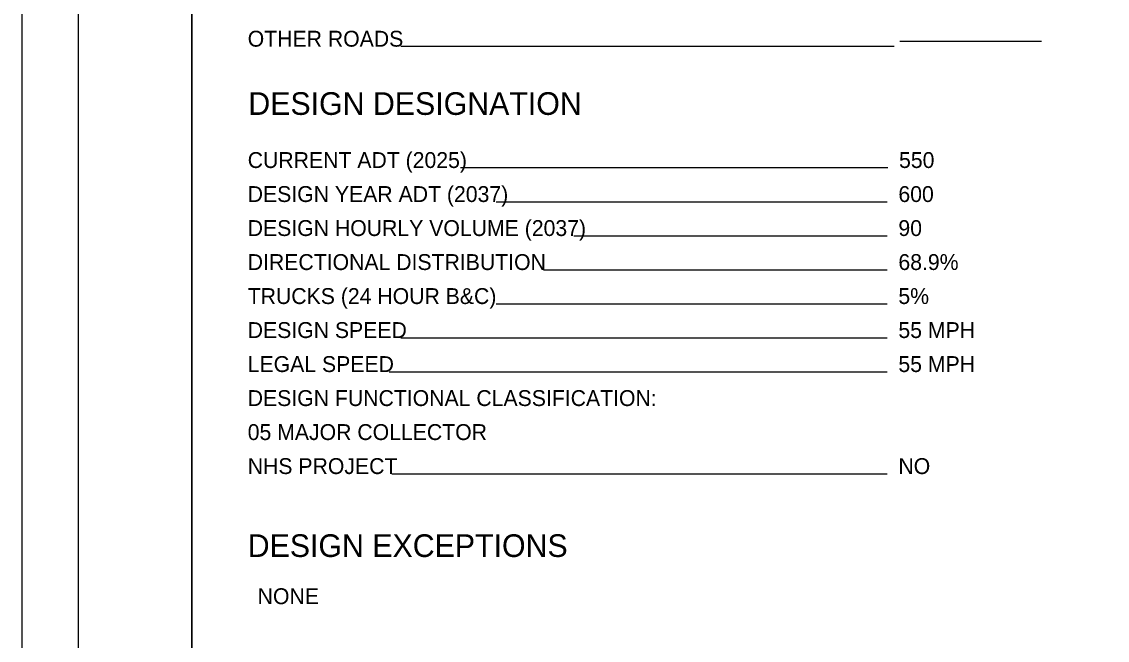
# Model space of a CAD drawing. Extents: x 0 to 82.7, y -0.2 to 22.
# Drawn here: x 0 to 9.58, y 5.64 to 11.1 of the extents above; entities that cross this region are included whole.
import ezdxf

# ---------------------------------------------------------------- set-up
doc = ezdxf.new("R2010")
doc.units = 0
for name, color, linetype in [('Default', 7, 'Continuous'), ('SH_Border', 7, 'Continuous'), ('SH_Cut_Line', 7, 'Continuous'), ('SH_Data', 7, 'Continuous'), ('SH_Text', 7, 'Continuous')]:
    doc.layers.add(name, color=color, linetype=linetype)

msp = doc.modelspace()

# ---------------------------------------------------------------- linework, layer by layer
at = {"layer": 'SH_Border'}
for points in [[(0.5, 21.5), (1.5, 21.5), (1.5, 0.5), (0.5, 0.5)], [(1.5, 21.5), (33.5, 21.5), (33.5, 0.5), (1.5, 0.5)]]:
    msp.add_lwpolyline(points, close=True, dxfattribs=at)
at = {"layer": 'SH_Cut_Line'}
msp.add_lwpolyline([(0, 0), (34, 0), (34, 22), (0, 22)], close=True, dxfattribs=at)
at = {"layer": 'SH_Data'}
for p, q in [((9, 10.9223), (7.75, 10.9223)), ((7.7, 10.8767), (3.3471, 10.8767)), ((7.6424, 9.8062), (3.871, 9.8062)), ((7.6368, 9.5062), (4.1885, 9.5062)), ((7.6368, 9.2062), (4.8723, 9.2062)), ((7.6368, 8.9062), (4.6037, 8.9062)), ((7.6368, 8.6062), (4.1885, 8.6062)), ((7.6368, 8.3062), (3.346, 8.3062)), ((7.6368, 8.0062), (3.2422, 8.0062)), ((7.6368, 7.1062), (3.2669, 7.1062))]:
    msp.add_line(p, q, dxfattribs=at)

# ---------------------------------------------------------------- texts
at = {"layer": 'Default'}
msp.add_text('NONE', height=0.14, dxfattribs=at).set_placement((2.0821, 5.9586))
at = {"layer": 'SH_Data'}
msp.add_text('DESIGN DESIGNATION', height=0.2, dxfattribs=at).set_placement((2, 10.2747))
at = {"layer": 'SH_Text'}
for s, height, p in [('OTHER ROADS', 0.14, (1.9944, 10.8767)), ('CURRENT ADT (2025)', 0.14, (1.9944, 9.8062)), ('550', 0.14, (7.7424, 9.8062)), ('DESIGN YEAR ADT (2037)', 0.14, (1.9944, 9.5062)), ('600', 0.14, (7.7368, 9.5062)), ('DESIGN HOURLY VOLUME (2037)', 0.14, (1.9944, 9.2062)), ('90', 0.14, (7.7368, 9.2062)), ('DIRECTIONAL DISTRIBUTION', 0.14, (1.9944, 8.9062)), ('68.9%', 0.14, (7.7368, 8.9062)), ('TRUCKS (24 HOUR B&C)', 0.14, (1.9944, 8.6062)), ('5%', 0.14, (7.7368, 8.6062)), ('DESIGN SPEED', 0.14, (1.9944, 8.3062)), ('55 MPH', 0.14, (7.7368, 8.3062)), ('LEGAL SPEED', 0.14, (1.9944, 8.0062)), ('55 MPH', 0.14, (7.7368, 8.0062)), ('DESIGN FUNCTIONAL CLASSIFICATION:', 0.14, (1.9944, 7.7062)), ('05 MAJOR COLLECTOR', 0.14, (1.9944, 7.4062)), ('NHS PROJECT', 0.14, (1.9944, 7.1062)), ('NO', 0.14, (7.7368, 7.1062)), ('DESIGN EXCEPTIONS', 0.2, (1.9944, 6.3744))]:
    msp.add_text(s, height=height, dxfattribs=at).set_placement(p)

doc.saveas('drawing.dxf')
